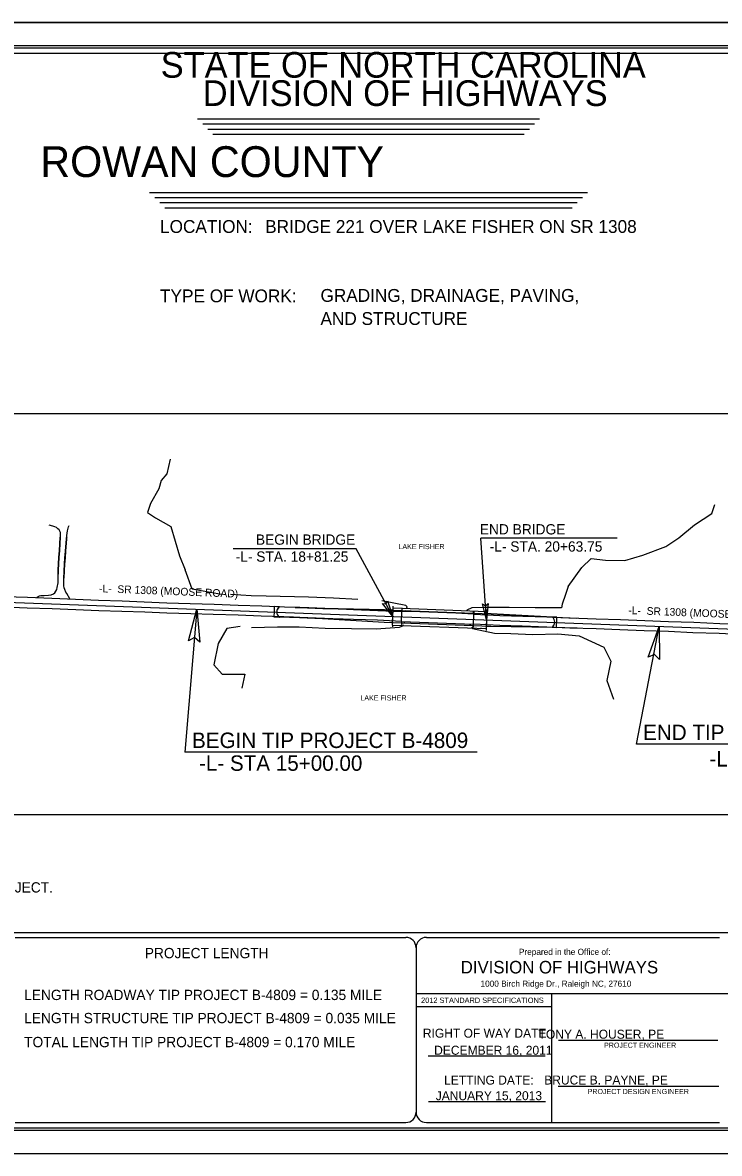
# Model space of a CAD drawing. Extents: x 1530800 to 1534168, y 642962 to 645162.
# Drawn here: x 1531959 to 1533314, y 642962 to 645162 of the extents above; entities that cross this region are included whole.
import ezdxf

# ---------------------------------------------------------------- set-up
doc = ezdxf.new("R2010")
doc.units = 0
for name, color, linetype in [('Exist Hydro Stream or Body of Water', 7, 'Continuous'), ('Exist Roads Curbs', 7, 'Continuous'), ('Exist Roads EOP', 7, 'Continuous'), ('Exist Roads EOP Other', 7, 'Continuous'), ('Exist Structure Major Bridge WW', 7, 'Continuous'), ('Exist Structure Major Deck Tunnel Box Culvert', 7, 'Continuous'), ('Old_Level_1', 7, 'Continuous'), ('Old_Level_11', 7, 'Continuous'), ('Old_Level_6', 7, 'Continuous'), ('Old_Level_8', 7, 'Continuous'), ('Prop EOT', 7, 'Continuous'), ('Prop Horizontal Alignment', 7, 'Continuous'), ('Prop Roadway Bridge', 7, 'Continuous'), ('Prop Shade Light', 7, 'Continuous'), ('Prop Shade Medium', 7, 'Continuous'), ('Sheet Cutting Line CELL', 7, 'Continuous'), ('Sheet Data Field CELL', 7, 'Continuous'), ('Sheet Plot Border Inside CELL', 7, 'Continuous'), ('Sheet Plot Border Outside CELL', 7, 'Continuous'), ('Sheet Title CELL', 7, 'Continuous'), ('Sheet Title Data Points CELL', 7, 'Continuous')]:
    doc.layers.add(name, color=color, linetype=linetype)

msp = doc.modelspace()

# ---------------------------------------------------------------- linework, layer by layer
at = {"layer": 'Exist Hydro Stream or Body of Water'}
for p, q in [((1532288.8, 644060.1), (1532275.4, 644097.6)), ((1533020.3, 644065.3), (1533014.9, 644049.6)), ((1532345.7, 644049.7), (1532288.8, 644060.1)), ((1533014.9, 644049.6), (1533008.6, 644031.1)), ((1533008.6, 644031.1), (1533007.2, 644023.4))]:
    msp.add_line(p, q, dxfattribs=at)
for points in [[(1532246, 644313.2), (1532239.4, 644284.6), (1532228.2, 644271.7), (1532223.8, 644255), (1532207.8, 644226.6), (1532201.6, 644209.1), (1532217.6, 644199.1), (1532247.5, 644182.1), (1532264.4, 644125.1), (1532275.4, 644097.6)], [(1533020.3, 644065.3), (1533046.8, 644102.4), (1533064.9, 644119.5), (1533092.8, 644116.6), (1533130.2, 644115.6), (1533165.4, 644126.1), (1533209.9, 644143.1), (1533235.3, 644160), (1533266.1, 644185.3), (1533299.7, 644207.5), (1533305.2, 644224.7)], [(1532611.2, 644039.8), (1532563.4, 644042.8), (1532515.2, 644044.5), (1532432.9, 644046.4), (1532403.5, 644047.1), (1532363.1, 644049.6)], [(1532705.9, 644022.6), (1532707.1, 644025.7), (1532704.3, 644028.4), (1532657.5, 644037.2)], [(1533007.2, 644023.4), (1532956.3, 644023.4), (1532905.7, 644024.6), (1532859.8, 644024.6), (1532832.5, 644023.8), (1532823.4, 644019.4), (1532823.3, 644016.9)], [(1532703.8, 644017.2), (1532704.7, 644019.4)], [(1532823.3, 644014.1), (1532823.2, 644013)], [(1532382.1, 643987.6), (1532356.4, 643983.3), (1532339.2, 643954), (1532331.1, 643912.8), (1532347.4, 643894.7), (1532391.4, 643894.9), (1532385.3, 643867.5)], [(1532404.1, 643985.6), (1532454.6, 643986.5), (1532497.1, 643986.6), (1532547.2, 643984.3), (1532598.8, 643983.3), (1532646.8, 643983.1), (1532692.3, 643986.3), (1532698.7, 643989), (1532699.8, 643991.5)], [(1532701.2, 643994.7), (1532702.3, 643997.2)], [(1532828.8, 643991.3), (1532830.3, 643989.1)], [(1532832.4, 643986.1), (1532834.1, 643983.7), (1532876.7, 643974.6), (1532908.4, 643973.5), (1532951.2, 643972), (1533000.1, 643972.9), (1533041.7, 643969.1), (1533089.8, 643947.4), (1533103.4, 643919.9), (1533095.3, 643882.6), (1533108.2, 643846.2)]]:
    msp.add_lwpolyline(points, dxfattribs=at)
at = {"layer": 'Exist Roads Curbs'}
for points in [[(1532027.9, 644083.1), (1532028.4, 644096.8), (1532028.8, 644109.3), (1532029.7, 644121.6), (1532030.4, 644135.2), (1532032.2, 644161.2)], [(1532040, 644081.7), (1532040.5, 644095.7), (1532041.3, 644108.4), (1532042.1, 644120.9), (1532043.1, 644134), (1532045.1, 644157.9), (1532045.3, 644160.7)]]:
    msp.add_lwpolyline(points, dxfattribs=at)
at = {"layer": 'Exist Roads EOP'}
for points in [[(1532696.7, 644016.1), (1532650, 644017.7), (1532602.8, 644019.9), (1532562.7, 644021.5), (1532515.6, 644023.5), (1532468.1, 644025.1), (1532424.1, 644027.1), (1532378, 644028.5), (1532331.3, 644030.1), (1532284.6, 644031.4), (1532239.6, 644033), (1532195.3, 644034.5), (1532152.7, 644036.4), (1532106.7, 644037.9), (1532061.6, 644039.7), (1532016.1, 644041.8), (1531968.6, 644043.5), (1531924.3, 644044.8)], [(1532696, 643997.3), (1532649.6, 643999.4), (1532602.8, 644001), (1532562.7, 644002.5), (1532513.6, 644004.3), (1532467.2, 644006), (1532422.9, 644007.4), (1532378.4, 644009.2), (1532329.9, 644010.9), (1532285.9, 644012), (1532239.2, 644013.5), (1532196.7, 644015), (1532152.2, 644016.7), (1532107.2, 644018.1), (1532062.2, 644019.9), (1532016.4, 644021.5), (1531967.9, 644023.3), (1531922.8, 644024.9)], [(1532837.2, 644011.2), (1532887.5, 644009), (1532932.2, 644007.8), (1532979.1, 644006), (1533024.3, 644004.3), (1533074.5, 644002.6), (1533122.3, 644001), (1533169.2, 643999.2), (1533215.3, 643997.3), (1533264.8, 643995.5), (1533315, 643993.2), (1533377.5, 643991.1)], [(1532836.8, 643992.3), (1532887, 643990.3), (1532930.7, 643988.8), (1532978.4, 643986.9), (1533023.5, 643984.9), (1533074.4, 643983.4), (1533120.9, 643981.7), (1533167.8, 643979.8), (1533215.1, 643978), (1533262.8, 643975.9), (1533314, 643974.1), (1533375.9, 643971.4)]]:
    msp.add_lwpolyline(points, dxfattribs=at)
at = {"layer": 'Exist Roads EOP Other'}
for points in [[(1532032.8, 644161.1), (1532032.9, 644166.5), (1532032.4, 644170), (1532031.4, 644172.8), (1532029.9, 644175.2), (1532027.3, 644177.6), (1532024.6, 644179.8), (1532021.6, 644181.6), (1532017.7, 644182.8), (1532010.6, 644184.3)], [(1532051.1, 644041.1), (1532044.7, 644051.3), (1532042.9, 644054.4), (1532041, 644059.4), (1532040, 644062.7), (1532039.3, 644066.6), (1532039, 644071), (1532039.1, 644080.2), (1532039.7, 644095.7), (1532040.5, 644108.5), (1532041.3, 644121), (1532042.3, 644134.1), (1532044.3, 644157.9), (1532044.8, 644164.3), (1532046.1, 644173.2), (1532048, 644181), (1532049.2, 644183.9)], [(1531986.8, 644043.6), (1531989, 644045.5), (1531991.7, 644046.8), (1531994.4, 644047.6), (1532000.7, 644047.9), (1532009.4, 644048.1), (1532014.6, 644049), (1532019.2, 644051), (1532021.7, 644053.2), (1532023.8, 644056.2), (1532025.3, 644059.6), (1532026.4, 644063.4), (1532027.8, 644072.3), (1532028.4, 644080.4), (1532029, 644096.8), (1532029.5, 644109.3), (1532030.3, 644121.6), (1532031.1, 644135.2), (1532032.8, 644161.1)]]:
    msp.add_lwpolyline(points, dxfattribs=at)
at = {"layer": 'Exist Structure Major Bridge WW'}
for points in [[(1532697.6, 644016.8), (1532697.6, 644021.1), (1532697.7, 644022.6), (1532696.9, 644022.7), (1532696.8, 644021.1), (1532696.8, 644016.8)], [(1532697.6, 644019.2), (1532697.6, 644019.2)], [(1532835.9, 644011.8), (1532836.1, 644015.9), (1532836.2, 644017.5), (1532837, 644017.4), (1532836.9, 644015.9), (1532836.8, 644011.7)], [(1532696, 643997.2), (1532695.8, 643992.9), (1532695.8, 643991.5), (1532696.6, 643991.4), (1532696.7, 643992.9), (1532696.7, 643997.2)], [(1532835.2, 643991.8), (1532834.9, 643987.8), (1532834.8, 643986.2), (1532835.7, 643986.3), (1532835.8, 643987.8), (1532835.9, 643991.8)]]:
    msp.add_lwpolyline(points, dxfattribs=at)
at = {"layer": 'Exist Structure Major Deck Tunnel Box Culvert'}
for p, q in [((1532696, 643997.2), (1532696.8, 644016.8)), ((1532836.2, 643991.8), (1532836.7, 644011.7))]:
    msp.add_line(p, q, dxfattribs=at)
for points in [[(1532836.7, 644011.7), (1532802, 644013.2), (1532766.6, 644014.4), (1532731.5, 644015.8), (1532696.8, 644016.8)], [(1532696, 643997.2), (1532731.1, 643995.7), (1532766.1, 643994.3), (1532801, 643993.2), (1532836.2, 643991.8)]]:
    msp.add_lwpolyline(points, dxfattribs=at)
at = {"layer": 'Old_Level_1'}
for p, q in [((1532861.5, 644000.1), (1532850.2, 644159)), ((1533115.8, 644159), (1532850.2, 644159)), ((1532608.1, 644138.3), (1532368.3, 644138.3)), ((1532679.1, 644006.9), (1532608.1, 644138.3)), ((1532298.1, 644021.2), (1532274.5, 643742.6)), ((1533152.9, 643758.2), (1533197.5, 643987.6)), ((1533672.5, 643758.2), (1533152.9, 643758.2)), ((1532843.1, 643742.6), (1532274.5, 643742.6))]:
    msp.add_line(p, q, dxfattribs=at)
at = {"layer": 'Old_Level_11'}
for points in [[(1532281.9, 643959.3), (1532298.1, 644021.2), (1532303.8, 643957.1), (1532293.4, 643966.1)], [(1532668.9, 644037.2), (1532679.1, 644006.9), (1532659.1, 644032.1), (1532665.9, 644031.3)], [(1532864.7, 644031.9), (1532861.5, 644000.1), (1532853.7, 644031.4), (1532859.6, 644027.7)], [(1533175.9, 643927.4), (1533197.5, 643987.6), (1533197.6, 643923.2), (1533188, 643933.1)]]:
    msp.add_lwpolyline(points, close=True, dxfattribs=at)
at = {"layer": 'Old_Level_6'}
msp.add_lwpolyline([(1531841.4, 644402.1), (1533536.6, 644402.1), (1533536.6, 643621.2), (1531841.4, 643621.2)], close=True, dxfattribs=at)
at = {"layer": 'Prop EOT'}
for p, q in [((1532488.9, 644024.4), (1532498.4, 644024.1)), ((1532498.4, 644024.1), (1532543.1, 644022.3)), ((1532543.1, 644022.3), (1532663.1, 644019.6)), ((1532485.8, 644005.3), (1532467, 644006)), ((1532485.8, 644005.3), (1532497.6, 644004.8)), ((1532497.6, 644004.8), (1532542.4, 644003.2)), ((1532542.4, 644003.2), (1532662.2, 643995.6)), ((1532663.1, 644019.6), (1532870.5, 644011.8)), ((1532870.5, 644011.8), (1532990.5, 644005.6)), ((1532990.5, 644005.6), (1533037.3, 644003.8)), ((1532662.2, 643995.6), (1532869.6, 643987.8)), ((1532869.6, 643987.8), (1532990.5, 643986.4)), ((1532990.5, 643986.4), (1533037.8, 643984.5))]:
    msp.add_line(p, q, dxfattribs=at)
at = {"layer": 'Prop Horizontal Alignment'}
msp.add_line((1531841.4, 644038.2), (1533531.9, 643975.1), dxfattribs=at)
at = {"layer": 'Prop Roadway Bridge'}
for p, q in [((1532678.5, 643990.2), (1532679.7, 644023.6)), ((1532679.7, 644023.6), (1532679.8, 644027.1)), ((1532679.7, 644023.6), (1532862.1, 644016.8)), ((1532862.1, 644016.8), (1532860.8, 643983.4)), ((1532862.1, 644016.8), (1532862.2, 644020.3)), ((1532678.5, 643990.2), (1532678.3, 643986.8)), ((1532678.5, 643990.2), (1532860.8, 643983.4)), ((1532860.8, 643983.4), (1532860.7, 643979.9))]:
    msp.add_line(p, q, dxfattribs=at)
at = {"layer": 'Prop Shade Light'}
for p, q in [((1532468.1, 644025.1), (1532458.7, 644025.5)), ((1532498.3, 644024.1), (1532468.1, 644025.1)), ((1532543.1, 644022.3), (1532498.3, 644024.1)), ((1532663.1, 644019.6), (1532543.1, 644022.3)), ((1532457.8, 644006.2), (1532497.6, 644004.8)), ((1532497.6, 644004.8), (1532497.6, 644004.8)), ((1532497.6, 644004.8), (1532497.6, 644004.8)), ((1532497.6, 644004.8), (1532497.6, 644004.8)), ((1532497.6, 644004.8), (1532542.4, 644003.2)), ((1532542.4, 644003.2), (1532662.2, 643995.6)), ((1532679.5, 644018.9), (1532663.1, 644019.6)), ((1532678.6, 643995), (1532679.5, 644018.9)), ((1532851.9, 644016.5), (1532851.9, 644016.5)), ((1532861.9, 644012.1), (1532861, 643988.1)), ((1532870.5, 644011.8), (1532861.9, 644012.1)), ((1532990.3, 644005.6), (1532870.5, 644011.8)), ((1532990.3, 644005.6), (1532989.9, 644005.6)), ((1532989.9, 644005.6), (1532990.3, 644005.6)), ((1532662.2, 643995.6), (1532678.6, 643995)), ((1532850.7, 643984.3), (1532850.7, 643984.5)), ((1532861, 643988.1), (1532869.6, 643987.8)), ((1532869.6, 643987.8), (1532989.3, 643986.4)), ((1532988.9, 643986), (1532989.6, 643986.4))]:
    msp.add_line(p, q, dxfattribs=at)
msp.add_lwpolyline([(1532497.6, 644004.8), (1532497.6, 644004.8)], dxfattribs=at)
for centre, radius, start, end in [((1532465.1, 644015.6), 11.8, 122.919, 231.8496), ((1532981.6, 643996.2), 12.5, 308.204, 48.4421)]:
    msp.add_arc(centre, radius, start, end, dxfattribs=at)
at = {"layer": 'Prop Shade Medium'}
for p, q in [((1532447.6, 644006.1), (1532458.5, 644005.7)), ((1532998, 644005.3), (1532989.9, 644005.6)), ((1532998, 644005.3), (1532989.9, 644005.6)), ((1532997.3, 643985.7), (1532998, 644005.3)), ((1532997.3, 643985.7), (1532998, 644005.3)), ((1532988.9, 643986), (1532997.3, 643985.7)), ((1532988.9, 643986), (1532997.3, 643985.7))]:
    msp.add_line(p, q, dxfattribs=at)
for points in [[(1532448.4, 644026.1), (1532448, 644016.3), (1532447.6, 644006.1)], [(1532458.9, 644025.6), (1532458.9, 644025.6), (1532448.4, 644026.1)]]:
    msp.add_lwpolyline(points, dxfattribs=at)
for centre, radius, start, end in [((1532465.1, 644015.6), 11.8, 121.8759, 235.9716), ((1532981.6, 643996.2), 12.5, 305.6815, 48.4421), ((1532981.6, 643996.2), 12.5, 305.6815, 48.4421)]:
    msp.add_arc(centre, radius, start, end, dxfattribs=at)
at = {"layer": 'Sheet Cutting Line CELL'}
for p, q in [((1530800.4, 645162.3), (1534168.4, 645162.3)), ((1530800.4, 642962.3), (1534168.4, 642962.3))]:
    msp.add_line(p, q, dxfattribs=at)
at = {"layer": 'Sheet Plot Border Inside CELL'}
msp.add_lwpolyline([(1530826.4, 643007.2), (1534159.4, 643007.2), (1534159.4, 645117.4), (1530826.4, 645117.4)], close=True, dxfattribs=at)
at = {"layer": 'Sheet Plot Border Outside CELL'}
for p, q in [((1534168.4, 645162.3), (1530800.4, 645162.3)), ((1530800.4, 642962.3), (1534168.4, 642962.3))]:
    msp.add_line(p, q, dxfattribs=at)
at = {"layer": 'Sheet Title CELL'}
for p, q in [((1532299.2, 644975.2), (1532964.7, 644975.2)), ((1532309.2, 644965.2), (1532954.7, 644965.2)), ((1532319.2, 644955.2), (1532944.7, 644955.2)), ((1532329.2, 644945.2), (1532934.7, 644945.2)), ((1532205.9, 644832), (1533057.9, 644832)), ((1532215.9, 644822), (1533047.9, 644822)), ((1532225.9, 644812), (1533037.9, 644812)), ((1532235.9, 644802), (1533027.9, 644802)), ((1531264.4, 643392.3), (1534104.4, 643392.3)), ((1531944.4, 643382.3), (1532704.4, 643382.3)), ((1532724.4, 643362.3), (1532724.4, 643042.3)), ((1532744.4, 643382.3), (1533314.4, 643382.3)), ((1533334.4, 643272.8), (1532724.4, 643272.8)), ((1532987.5, 643272.8), (1532987.5, 643022.3)), ((1532987.5, 643247.3), (1532724.4, 643247.3)), ((1532911.7, 643247.3), (1532911.7, 643247.3)), ((1533001.3, 643182.8), (1533311.6, 643182.8)), ((1532975.5, 643151.6), (1532748, 643151.6)), ((1532861.7, 643151.6), (1532861.7, 643151.6)), ((1533000.6, 643092.8), (1533313.1, 643092.8)), ((1532976.3, 643062.4), (1532748.8, 643062.4))]:
    msp.add_line(p, q, dxfattribs=at)
for points in [[(1534114.4, 645112.3), (1531154.3, 645112.3)], [(1534104.4, 645102.3), (1531264.4, 645102.3)], [(1531154.4, 643012.3), (1534114.4, 643012.3)], [(1531944.4, 643022.3), (1532704.4, 643022.3)], [(1532744.4, 643022.3), (1533314.4, 643022.3)]]:
    msp.add_lwpolyline(points, dxfattribs=at)
for centre, start, end in [((1532704.4, 643362.4), 0, 90), ((1532744.4, 643362.4), 90, 180), ((1532704.4, 643042.4), 270, 360), ((1532744.4, 643042.4), 180, 270)]:
    msp.add_arc(centre, 20, start, end, dxfattribs=at)
at = {"layer": 'Sheet Title Data Points CELL'}
for p, q in [((1532635, 644861.8), (1532635, 644861.8)), ((1532875.1, 644753.1), (1532875.1, 644753.1))]:
    msp.add_line(p, q, dxfattribs=at)

# ---------------------------------------------------------------- texts
at = {"layer": 'Old_Level_1'}
for s, height, rotation, p in [('  END BRIDGE', 20, 360, (1532833.5, 644166.5)), ('BEGIN BRIDGE', 20, 359.9999, (1532412.8, 644146.5)), ('-L- STA. 20+63.75', 20, 360, (1532867.5, 644133.1)), ('-L- STA. 18+81.25', 20, 359.9999, (1532373.4, 644113.4)), ('-L-  SR 1308 (MOOSE ROAD)', 15, 357.7581, (1532107.4, 644054.1)), ('-L-  SR 1308 (MOOSE ROAD)', 15, 357.7581, (1533137, 644011.7)), ('BEGIN TIP PROJECT B-4809', 30, 360, (1532288.5, 643751)), ('END TIP PROJECT B-4809', 30, 360, (1533166, 643766.3)), ('-L- STA 15+00.00', 30, 360, (1532302.1, 643706.6)), ('-L- STA 24+00.00', 30, 360, (1533295.1, 643715)), ('THERE IS NO CONTROL OF ACCESS ON THIS PROJECT.', 20, 360, (1531291.3, 643469.8)), ('LENGTH ROADWAY TIP PROJECT B-4809 = 0.135 MILE', 20, 360, (1531961.9, 643260.6)), ('LENGTH STRUCTURE TIP PROJECT B-4809 = 0.035 MILE', 20, 360, (1531961.9, 643215.6)), ('TOTAL LENGTH TIP PROJECT B-4809 = 0.170 MILE', 20, 360, (1531961.9, 643168.9))]:
    msp.add_text(s, height=height, rotation=rotation, dxfattribs=at).set_placement(p)
at = {"layer": 'Old_Level_8'}
for p in [(1532690.1, 644137.9), (1532616, 643843.5)]:
    msp.add_text('LAKE FISHER', height=10, rotation=359.9999, dxfattribs=at).set_placement(p)
at = {"layer": 'Sheet Data Field CELL'}
for s, height, p in [('         ROWAN COUNTY        ', 60, (1531792.8, 644861.8)), ('BRIDGE 221 OVER LAKE FISHER ON SR 1308  ', 25, (1532430.8, 644753.1)), ('GRADING, DRAINAGE, PAVING,              ', 25, (1532538.4, 644619)), ('AND STRUCTURE                           ', 25, (1532538.4, 644574)), ('      TONY A. HOUSER, PE          ', 17.5, (1532923.6, 643185.4)), ('DECEMBER 16, 2011', 17.5, (1532759.5, 643154.2)), ('      BRUCE B. PAYNE, PE          ', 17.5, (1532934.6, 643096.3)), ('JANUARY 15, 2013', 17.5, (1532762.6, 643065.8))]:
    msp.add_text(s, height=height, dxfattribs=at).set_placement(p)
at = {"layer": 'Sheet Title CELL'}
for s, height, p in [('STATE OF NORTH CAROLINA', 50, (1532227.6, 645055.1)), ('DIVISION OF HIGHWAYS', 50, (1532309.4, 645000.1)), ('LOCATION: ', 25, (1532226.3, 644753.1)), ('TYPE OF WORK:', 25, (1532226.3, 644618.1)), ('PROJECT LENGTH', 19.999, (1532196.6, 643342)), ('Prepared in the Office of:', 11.999, (1532924.4, 643348.4)), ('DIVISION OF HIGHWAYS', 24.374, (1532811.3, 643312.4)), ('1000 Birch Ridge Dr., Raleigh NC, 27610', 12, (1532849.7, 643286.5)), ('2012 STANDARD SPECIFICATIONS', 10.4, (1532734.1, 643255)), ('RIGHT OF WAY DATE: ', 17.5, (1532737.5, 643187.4)), ('PROJECT ENGINEER', 9.999, (1533090, 643167.8)), ('LETTING DATE:', 17.5, (1532778.8, 643096.1)), ('PROJECT DESIGN ENGINEER', 9.999, (1533058, 643077.7))]:
    msp.add_text(s, height=height, dxfattribs=at).set_placement(p)

doc.saveas('drawing.dxf')
